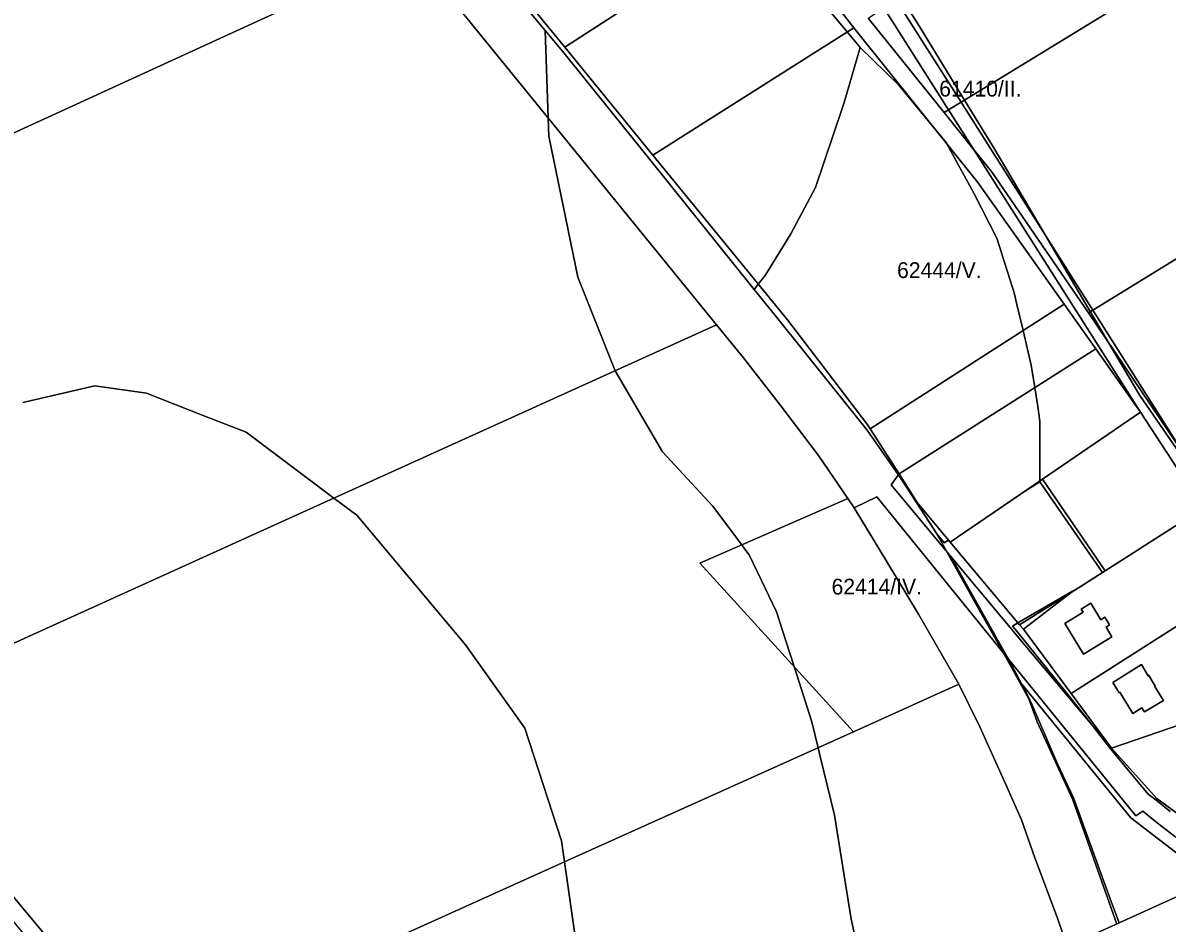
# Model space of a CAD drawing. Extents: x -522079 to -518833, y -1142400 to -1139961.
# Drawn here: x -520985.3 to -520623.1, y -1140806 to -1140520.9 of the extents above; entities that cross this region are included whole.
import ezdxf

# ---------------------------------------------------------------- set-up
doc = ezdxf.new("R2010")
doc.units = 0
for name, color, linetype in [('95560013', 7, 'Continuous'), ('95590013', 7, 'Continuous'), ('95610013', 7, 'Continuous'), ('95640013', 7, 'Continuous'), ('95660013', 7, 'Continuous')]:
    doc.layers.add(name, color=color, linetype=linetype)

msp = doc.modelspace()

# ---------------------------------------------------------------- linework, layer by layer
at = {"layer": '95560013'}
for points in [[(-521174.07, -1140567.72), (-521038.29, -1140505.39), (-520903.84, -1140443.54), (-520902.4, -1140445.74), (-520890.58, -1140462.46), (-520871.65, -1140486.28), (-520862.22, -1140497.87), (-521134.28, -1140622.71), (-521175.11, -1140573.76)], [(-520837.71, -1140499.35), (-520772.84, -1140457.31), (-520749.72, -1140487.1), (-520813.81, -1140528.62)], [(-520785.9, -1140562.81), (-520813.81, -1140528.62), (-520749.72, -1140487.1), (-520722.28, -1140522.46), (-520735.82, -1140531.09)], [(-520862.22, -1140497.87), (-520765.71, -1140616.57), (-520897.82, -1140676.39), (-521036.95, -1140739.4), (-521134.28, -1140622.71)], [(-520712.75, -1140516.21), (-520692.27, -1140548.47), (-520693.7, -1140549.35), (-520717.71, -1140519.42)], [(-520722.28, -1140522.46), (-520682.96, -1140571.47), (-520655.7, -1140609.99), (-520717.09, -1140649.55), (-520718.15, -1140647.9), (-520730.64, -1140631.58), (-520743.28, -1140615.01), (-520785.9, -1140562.81), (-520735.82, -1140531.09)], [(-520693.7, -1140549.35), (-520692.27, -1140548.47), (-520684.19, -1140561.2)], [(-521187.8, -1140573.75), (-521174.07, -1140567.72), (-521175.11, -1140573.76), (-521134.28, -1140622.71), (-521036.95, -1140739.4), (-520947.33, -1140846.85), (-520890.08, -1140915.49), (-520882.47, -1140917.37), (-520896.33, -1140923.45), (-520894.6, -1140917.89), (-520952.05, -1140848.96), (-521041.47, -1140741.65), (-521139.09, -1140624.65), (-521179.71, -1140575.8)], [(-520655.7, -1140609.99), (-520645.69, -1140624.14), (-520707.94, -1140663.79), (-520717.09, -1140649.55)], [(-521036.95, -1140739.4), (-520897.82, -1140676.39), (-520765.71, -1140616.57), (-520757.18, -1140627.06), (-520745.42, -1140642.26), (-520733.42, -1140657.97), (-520724.12, -1140671.61), (-520771, -1140692.05), (-520722.34, -1140745.4), (-520809.38, -1140784.65), (-520947.33, -1140846.85)], [(-520702.26, -1140672.84), (-520707.94, -1140663.79), (-520645.69, -1140624.14), (-520631.48, -1140644.23), (-520662.52, -1140665.44), (-520691.74, -1140685.4)], [(-520722.34, -1140745.4), (-520771, -1140692.05), (-520724.12, -1140671.61), (-520722.11, -1140674.56), (-520711.88, -1140691.39), (-520701.8, -1140708.2), (-520689.02, -1140730.38)], [(-520752.69, -1140853.85), (-520890.08, -1140915.49), (-520947.33, -1140846.85), (-520809.38, -1140784.65), (-520722.34, -1140745.4), (-520689.02, -1140730.38), (-520682.43, -1140743.84), (-520674.16, -1140762.17), (-520669.15, -1140773.31), (-520664.94, -1140785.33), (-520657.77, -1140804.5), (-520656.02, -1140809.72)]]:
    msp.add_lwpolyline(points, close=True, dxfattribs=at)
msp.add_lwpolyline([(-520717.71, -1140519.42), (-520693.7, -1140549.35), (-520684.19, -1140561.2), (-520631.48, -1140644.23), (-520645.69, -1140624.14), (-520655.7, -1140609.99), (-520682.96, -1140571.47), (-520722.28, -1140522.46), (-520749.72, -1140487.1)], dxfattribs=at)
at = {"layer": '95590013'}
for points in [[(-520662.52, -1140665.44), (-520631.48, -1140644.23), (-520611.7, -1140674.57), (-520642.72, -1140694.43)], [(-520653.49, -1140733.31), (-520668.57, -1140712.91), (-520653.44, -1140701.29), (-520642.72, -1140694.43), (-520611.7, -1140674.57), (-520608.35, -1140679.79), (-520599.29, -1140698.77)], [(-520640.71, -1140750.61), (-520653.49, -1140733.31), (-520599.29, -1140698.77), (-520583.71, -1140731.03), (-520593.04, -1140734.3)], [(-520653.44, -1140701.29), (-520668.57, -1140712.91), (-520669.79, -1140711.59)], [(-520655.5, -1140711.11), (-520649.51, -1140720.81), (-520640.64, -1140715.35), (-520642.42, -1140712.34), (-520641.28, -1140711.57), (-520642.78, -1140709.18), (-520644.04, -1140709.99), (-520647.28, -1140704.72), (-520650.3, -1140706.56), (-520649.68, -1140707.57)], [(-520624.28, -1140735.5), (-520627, -1140731.07), (-520626.83, -1140730.97), (-520628.87, -1140727.65), (-520629.04, -1140727.75), (-520631.24, -1140724.18), (-520640.31, -1140729.84), (-520638.3, -1140733.1), (-520638.05, -1140732.94), (-520633.92, -1140739.62), (-520631.05, -1140737.86), (-520630.26, -1140739.15)]]:
    msp.add_lwpolyline(points, close=True, dxfattribs=at)
msp.add_lwpolyline([(-520614.11, -1140775.58), (-520626.37, -1140766.52), (-520640.71, -1140750.61), (-520593.04, -1140734.3)], dxfattribs=at)
at = {"layer": '95610013'}
for points in [[(-520686.89, -1140499.45), (-520675.92, -1140498.77), (-520661.91, -1140491.42), (-520635.69, -1140488.94), (-520617.72, -1140496.63), (-520614.24, -1140500.69), (-520688.32, -1140546.05), (-520708.82, -1140513.67)], [(-520688.32, -1140546.05), (-520614.24, -1140500.69), (-520587.68, -1140531.64), (-520567.56, -1140556.74), (-520562.84, -1140560.36), (-520646.64, -1140611.87)], [(-520515.8, -1140596.49), (-520617.05, -1140658.61), (-520646.64, -1140611.87), (-520562.84, -1140560.36), (-520525.93, -1140589.59)]]:
    msp.add_lwpolyline(points, close=True, dxfattribs=at)
at = {"layer": '95640013'}
for points in [[(-520837.71, -1140499.35), (-520813.81, -1140528.62), (-520785.9, -1140562.81), (-520743.28, -1140615.01), (-520730.64, -1140631.58), (-520718.15, -1140647.9), (-520717.09, -1140649.55), (-520707.94, -1140663.79), (-520710.41, -1140667.24), (-520694.71, -1140686.16), (-520691.52, -1140689.98), (-520673.31, -1140722.41), (-520715.02, -1140671.04), (-520722.11, -1140674.56), (-520724.12, -1140671.61), (-520733.42, -1140657.97), (-520745.42, -1140642.26), (-520757.18, -1140627.06), (-520765.71, -1140616.57), (-520862.22, -1140497.87)], [(-520620.79, -1140778.52), (-520626.26, -1140774.29), (-520630.76, -1140770.61), (-520632.98, -1140772.07), (-520673.31, -1140722.41), (-520691.52, -1140689.98), (-520667.53, -1140718.71), (-520640.71, -1140750.61), (-520626.37, -1140766.52), (-520614.11, -1140775.58)], [(-520987.34, -1140960.66), (-520896.33, -1140923.45), (-520882.47, -1140917.37), (-520708.35, -1140837.86), (-520654.73, -1140813.47), (-520638.22, -1140805.93), (-520618.93, -1140797.21)]]:
    msp.add_lwpolyline(points, dxfattribs=at)
for points in [[(-520708.82, -1140513.67), (-520688.32, -1140546.05), (-520692.27, -1140548.47), (-520712.75, -1140516.21)], [(-520688.32, -1140546.05), (-520646.64, -1140611.87), (-520648.02, -1140612.72), (-520678.73, -1140568), (-520684.19, -1140561.2), (-520692.27, -1140548.47)], [(-520581.36, -1140753.24), (-520579.16, -1140744.51), (-520580.56, -1140740.45), (-520583.71, -1140731.03), (-520599.29, -1140698.77), (-520608.35, -1140679.79), (-520611.7, -1140674.57), (-520631.48, -1140644.23), (-520684.19, -1140561.2), (-520678.73, -1140568), (-520648.02, -1140612.72), (-520617.05, -1140658.61), (-520605.12, -1140676.44), (-520598.21, -1140690.89), (-520586.97, -1140713.22), (-520580.64, -1140725.97), (-520577.29, -1140732.42), (-520576.44, -1140734.91), (-520575.25, -1140739.5), (-520574.04, -1140754.01), (-520579.46, -1140756.88), (-520580.35, -1140753)], [(-520646.64, -1140611.87), (-520617.05, -1140658.61), (-520648.02, -1140612.72)], [(-520691.52, -1140689.98), (-520694.71, -1140686.16), (-520710.41, -1140667.24), (-520707.94, -1140663.79), (-520702.26, -1140672.84), (-520691.74, -1140685.4), (-520669.79, -1140711.59), (-520668.57, -1140712.91), (-520653.49, -1140733.31), (-520640.71, -1140750.61), (-520667.53, -1140718.71)], [(-520691.74, -1140685.4), (-520662.52, -1140665.44), (-520642.72, -1140694.43), (-520653.44, -1140701.29), (-520669.79, -1140711.59)], [(-520657.77, -1140804.5), (-520664.94, -1140785.33), (-520669.15, -1140773.31), (-520674.16, -1140762.17), (-520682.43, -1140743.84), (-520689.02, -1140730.38), (-520701.8, -1140708.2), (-520711.88, -1140691.39), (-520722.11, -1140674.56), (-520715.02, -1140671.04), (-520673.31, -1140722.41), (-520669.12, -1140730.36), (-520666.3, -1140735.71), (-520657.82, -1140755.57), (-520652.69, -1140766.32), (-520641.11, -1140798.37), (-520638.22, -1140805.93), (-520654.73, -1140813.47), (-520656.02, -1140809.72)], [(-520655.5, -1140711.11), (-520649.68, -1140707.57), (-520650.3, -1140706.56), (-520647.28, -1140704.72), (-520644.04, -1140709.99), (-520642.78, -1140709.18), (-520641.28, -1140711.57), (-520642.42, -1140712.34), (-520640.64, -1140715.35), (-520649.51, -1140720.81)], [(-520594.41, -1140790.88), (-520595.39, -1140795.43), (-520616.33, -1140786.69), (-520634.59, -1140772.65), (-520669.12, -1140730.36), (-520673.31, -1140722.41), (-520632.98, -1140772.07), (-520630.76, -1140770.61), (-520626.26, -1140774.29), (-520620.79, -1140778.52), (-520609.47, -1140785.27), (-520604.74, -1140787.54), (-520595.11, -1140790.67)], [(-520624.28, -1140735.5), (-520630.26, -1140739.15), (-520631.05, -1140737.86), (-520633.92, -1140739.62), (-520638.05, -1140732.94), (-520638.3, -1140733.1), (-520640.31, -1140729.84), (-520631.24, -1140724.18), (-520629.04, -1140727.75), (-520628.87, -1140727.65), (-520626.83, -1140730.97), (-520627, -1140731.07)], [(-520616.33, -1140786.69), (-520618.93, -1140797.21), (-520638.22, -1140805.93), (-520641.11, -1140798.37), (-520652.69, -1140766.32), (-520657.82, -1140755.57), (-520666.3, -1140735.71), (-520669.12, -1140730.36), (-520634.59, -1140772.65)]]:
    msp.add_lwpolyline(points, close=True, dxfattribs=at)
at = {"layer": '95660013'}
for points in [[(-520748.55, -1140494.92), (-520724.41, -1140523.82), (-520720.3, -1140528.75), (-520725.31, -1140546.11), (-520725.95, -1140548.02), (-520734.42, -1140573.08), (-520742.17, -1140587.7), (-520750.37, -1140600.96), (-520752.51, -1140603.7), (-520753.81, -1140605.37), (-520787.26, -1140563.73), (-520814.48, -1140529.93), (-520819.98, -1140523.33), (-520838.57, -1140501.03)], [(-520622.14, -1140770.72), (-520626.64, -1140767.02), (-520629.12, -1140765.19), (-520640.92, -1140750.89), (-520647.27, -1140742.8), (-520654.49, -1140733.61), (-520670.7, -1140713.58), (-520672, -1140711.97), (-520670.3, -1140710.98), (-520657.77, -1140703.65), (-520653.29, -1140701.03), (-520650.65, -1140699.51), (-520643.54, -1140694.95), (-520663.43, -1140666.27), (-520663.43, -1140666.06), (-520663.35, -1140647.12), (-520664.07, -1140642.39), (-520664.98, -1140636.43), (-520666.08, -1140629.29), (-520668.69, -1140618.36), (-520670.67, -1140610.09), (-520671.55, -1140606.44), (-520677.01, -1140589.08), (-520684.3, -1140574.91), (-520692.8, -1140559.2), (-520692.96, -1140558.91), (-520696.06, -1140555.15), (-520708, -1140540.63), (-520720.3, -1140528.75), (-520724.41, -1140523.82), (-520748.55, -1140494.92)], [(-520838.57, -1140501.03), (-520819.98, -1140523.33), (-520819.04, -1140550.97), (-520818.85, -1140556.8), (-520809.67, -1140601.52), (-520797.86, -1140631.12), (-520782.79, -1140656.77), (-520767.05, -1140673.87), (-520757.77, -1140686.28), (-520756.78, -1140687.61), (-520755.74, -1140689.01), (-520755.49, -1140689.33), (-520755.25, -1140689.65), (-520746.73, -1140707.41), (-520743.67, -1140716.97), (-520741.19, -1140724.73), (-520735.59, -1140742.26), (-520733.59, -1140750.47), (-520733.24, -1140751.9), (-520732.79, -1140753.72), (-520728.37, -1140771.86), (-520723.13, -1140804.75), (-520719.2, -1140822.5)], [(-520603.38, -1140680.08), (-520631.76, -1140638.92), (-520641.51, -1140622.36), (-520647.41, -1140612.34), (-520655.76, -1140598.17), (-520661.74, -1140588.03), (-520677.61, -1140561.08), (-520687.24, -1140545.38), (-520701.19, -1140522.65), (-520707.3, -1140512.68)], [(-520707.3, -1140512.68), (-520701.19, -1140522.65), (-520687.24, -1140545.38), (-520677.61, -1140561.08), (-520661.74, -1140588.03), (-520655.76, -1140598.17), (-520647.41, -1140612.34), (-520641.51, -1140622.36), (-520631.76, -1140638.92), (-520603.38, -1140680.08)], [(-520719.2, -1140822.5), (-520723.13, -1140804.75), (-520728.37, -1140771.86), (-520732.79, -1140753.72), (-520733.24, -1140751.9), (-520733.59, -1140750.47), (-520735.59, -1140742.26), (-520741.19, -1140724.73), (-520743.67, -1140716.97), (-520746.73, -1140707.41), (-520755.25, -1140689.65), (-520755.49, -1140689.33), (-520755.74, -1140689.01), (-520756.78, -1140687.61), (-520757.77, -1140686.28), (-520767.05, -1140673.87), (-520782.79, -1140656.77), (-520797.86, -1140631.12), (-520809.67, -1140601.52), (-520818.85, -1140556.8), (-520819.04, -1140550.97), (-520819.98, -1140523.33), (-520814.48, -1140529.93), (-520787.26, -1140563.73), (-520753.81, -1140605.37), (-520747.51, -1140613.22), (-520718.06, -1140649.96), (-520708.2, -1140663.95), (-520708.13, -1140664.05), (-520698.31, -1140679.15), (-520695.97, -1140682.74), (-520695.28, -1140683.98), (-520692.78, -1140688.47), (-520682.03, -1140707.78), (-520675.14, -1140720.16), (-520666.9, -1140734.95), (-520664.27, -1140742.26), (-520652.97, -1140767), (-520639.05, -1140806.31)], [(-520985.36, -1140641.14), (-520962.58, -1140635.86), (-520946.22, -1140638.21), (-520929.07, -1140644.91), (-520914.68, -1140650.52), (-520886.88, -1140671.43), (-520879.63, -1140676.88), (-520845.16, -1140717.91), (-520826.47, -1140744.28), (-520814.79, -1140780.02), (-520813.84, -1140786.66), (-520810.7, -1140808.74)], [(-520810.7, -1140808.74), (-520813.84, -1140786.66), (-520814.79, -1140780.02), (-520826.47, -1140744.28), (-520845.16, -1140717.91), (-520879.63, -1140676.88), (-520886.88, -1140671.43), (-520914.68, -1140650.52), (-520929.07, -1140644.91), (-520946.22, -1140638.21), (-520962.58, -1140635.86), (-520985.36, -1140641.14)], [(-520639.05, -1140806.31), (-520652.97, -1140767), (-520664.27, -1140742.26), (-520666.9, -1140734.95), (-520675.14, -1140720.16), (-520682.03, -1140707.78), (-520692.78, -1140688.47), (-520695.28, -1140683.98), (-520695.97, -1140682.74), (-520693.66, -1140685.62), (-520692.29, -1140684.74), (-520691.74, -1140685.4), (-520668.27, -1140669.37), (-520663.43, -1140666.27), (-520643.54, -1140694.95), (-520650.65, -1140699.51), (-520653.29, -1140701.03), (-520657.77, -1140703.65), (-520670.3, -1140710.98), (-520672, -1140711.97), (-520670.7, -1140713.58), (-520654.49, -1140733.61), (-520647.27, -1140742.8), (-520640.92, -1140750.89), (-520629.12, -1140765.19), (-520626.64, -1140767.02), (-520622.14, -1140770.72)]]:
    msp.add_lwpolyline(points, dxfattribs=at)
msp.add_lwpolyline([(-520663.43, -1140666.27), (-520668.27, -1140669.37), (-520691.74, -1140685.4), (-520692.29, -1140684.74), (-520693.66, -1140685.62), (-520695.97, -1140682.74), (-520698.31, -1140679.15), (-520708.13, -1140664.05), (-520708.2, -1140663.95), (-520718.06, -1140649.96), (-520747.51, -1140613.22), (-520753.81, -1140605.37), (-520752.51, -1140603.7), (-520750.37, -1140600.96), (-520742.17, -1140587.7), (-520734.42, -1140573.08), (-520725.95, -1140548.02), (-520725.31, -1140546.11), (-520720.3, -1140528.75), (-520708, -1140540.63), (-520696.06, -1140555.15), (-520692.96, -1140558.91), (-520692.8, -1140559.2), (-520684.3, -1140574.91), (-520677.01, -1140589.08), (-520671.55, -1140606.44), (-520670.67, -1140610.09), (-520668.69, -1140618.36), (-520666.08, -1140629.29), (-520664.98, -1140636.43), (-520664.07, -1140642.39), (-520663.35, -1140647.12), (-520663.43, -1140666.06)], close=True, dxfattribs=at)

# ---------------------------------------------------------------- texts
for s, rotation, p in [('61410/II.', 360, (-520695.23, -1140544.26)), ('62444/V.', 0, (-520708.58, -1140601.74)), ('62414/IV.', 0, (-520729.31, -1140701.96))]:
    msp.add_text(s, height=5, rotation=rotation, dxfattribs=at).set_placement(p)

doc.saveas('drawing.dxf')
